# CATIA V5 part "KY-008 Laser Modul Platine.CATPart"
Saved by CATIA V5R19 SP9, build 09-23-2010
Part number: KY-008 Laser Modul Platine
Bounding box of the stored display mesh (mm): x -7.5 to 7.5, y 0 to 19, z 0 to 1.6
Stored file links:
  D:\Temporäre Sachen\Lasermodul KY-008 with mounting for adjustment\KY-008 Laser Modul Platine.CATPart
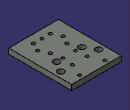
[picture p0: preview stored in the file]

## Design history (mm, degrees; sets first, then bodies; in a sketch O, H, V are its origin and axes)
Parameters
  inch2mm = 2.54 mm
Body1 (main body)
  Sketch1 on xy-plane, origin (0, 0, 0), H (1, 0, 0), V (0, 1, 0)
    point P1 (-7.5, 0)
    line L1 (-7.5, 0) -> (7.5, 0)
    line L2 (7.5, 0) -> (7.5, 19)
    line L3 (7.5, 19) -> (-7.5, 19)
    line L4 (-7.5, 19) -> (-7.5, 0)
    distance L1 L3 = 19
    distance L2 L4 = 15
    coincidence: P1 H
    horizontal: L1 H, L3 H
    vertical: L2 V, L4 V
    symmetry: L4 L2 V
  Pad1: profile Sketch1, direction (0, 0, 1), length 1.6
  Sketch2 on xy-plane, origin (0, 0, 0), H (1, 0, 0), V (0, 1, 0)
    construction line L1 (-3.81, 17.78) -> (3.81, 17.78)
    point P1 (-3.81, 17.78)
    point P2 (3.81, 17.78)
    point P3 (3.81, 5.08)
    point P4 (-3.81, 5.08)
    construction line L2 (-3.81, 5.08) -> (3.81, 5.08)
    point P5 (5.715, 13.97)
    point P6 (-5.715, 13.97)
    construction line L3 (-5.715, 13.97) -> (5.715, 13.97)
    point P7 (-2.25, 13.97)
    point P8 (2.25, 13.97)
    point P9 (3.81, 10.78)
    point P10 (-3.81, 10.78)
    construction line L4 (-3.81, 10.78) -> (3.81, 10.78)
    axis line L5 (-2.54, 2.54) -> (2.54, 2.54)
    point P13 (0, 2.54)
    construction line L6 (2.54, 2.54) -> (-2.54, 2.54)
    point P14 (1.905, 10.78)
    point P15 (-1.905, 10.78)
    point P16 (2.54, 7.62)
    point P17 (-2.54, 7.62)
    construction line L7 (-2.54, 7.62) -> (2.54, 7.62)
    length L1 = 7.62 {= 3*inch2mm}
    distance H L1 = 17.78 {= 7*inch2mm}
    length L2 = 7.62 {= Sketch2.length(L1)}
    distance L2 L1 = 12.7 {= 5*inch2mm}
    length L3 = 11.43 {= 4.5*inch2mm}
    distance P7 P8 = 4.5
    distance L1 L3 = 3.81 {= 1.5*inch2mm}
    length L4 = 7.62 {= 3*inch2mm}
    distance L1 L4 = 7
    distance P13 V = 0
    length L6 = 5.08 {= 2*inch2mm}
    distance P14 P15 = 3.81 {= 1.5*inch2mm}
    distance L1 L6 = 15.24 {= 6*inch2mm}
    length L7 = 5.08 {= 2*inch2mm}
    distance L1 L7 = 10.16 {= 4*inch2mm}
    horizontal: L1 H, L2 H, L3 H, L4 H, L5 H
    symmetry: P2 P1 V, P4 P3 V, P6 P5 V, P8 P7 V, P9 P10 V, P15 P14 V, P17 P16 V
    coincidence: P7 L3, P8 L3, P14 L4, P15 L4
    midpoint: P13 L6
  Sketch3 on end face of Pad1, origin (3.81, 10.78, 1.6), H (1, 0, 0), V (0, 1, 0)
    point P1 (0, 0)
    reference projected point E1 (0, 0) from Sketch2.P9
    coincidence: E1 P1
  Hole1: placed by Sketch3, at (3.81, 10.78, 1.6) direction (0, 0, -1), diameter 2, depth 3
  UserPattern1: of Hole1, copies 17, at the points of Sketch2
  Sketch4 on end face of Pad1, origin (3.81, 17.78, 1.6), H (1, 0, 0), V (0, 1, 0)
    point P1 (0, 0)
    reference projected point E1 (0, 0) from Sketch2.P2
    coincidence: E1 P1
  Hole2: placed by Sketch4, at (3.81, 17.78, 1.6) direction (0, 0, -1), diameter 1, depth 3
  UserPattern2: of Hole2, copies 17, at the points of Sketch2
